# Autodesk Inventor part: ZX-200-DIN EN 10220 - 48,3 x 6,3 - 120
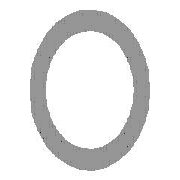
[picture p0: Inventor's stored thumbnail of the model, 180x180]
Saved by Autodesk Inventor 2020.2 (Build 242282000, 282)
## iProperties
Manager: www.cadconsulting.pl
Company: Fabian Stasiak CAD Consulting
IsCustomPart: 1
Created: 2015-02
Part Number: ZX-200-DIN EN 10220 - 48,3 x 6,3 - 120
Material: Stal, miękka
Description: Rury spawane bez szwu - Szereg 1
Document SubType Name: Modeling
Standard: DIN EN 10220
Designer: F.Stasiak
Standard Revision: 2003-03
Standards Organization: DIN
Language: pl-PL
Size Designation: 60,3 x 5,4 - 120
Categories: <MemberInstance><Categories><Category DisplayName="Kształtowniki konstrukcyjne" InternalName="089c4875-fa83-4c05-b084-43b9cc11f5ed" Mnemonic="GRDR"><CategoryPar
Stock Number: 60,3 x 5,4
Density: 7.85 g/cm^3
Appearance: Częściowo polerowany
Catalog Web Link: www.expertbooks.pl
G_L: 120,000 mm
Author: F.Stasiak
Subject: Zbiór ćwiczeń. Autodesk Inventor 2020. Kurs Professional
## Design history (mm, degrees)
node "Płaszczyzna początkowa"
node "Płaszczyzna końcowa"
sketch "Szkic"
  geometry: C1 r 24.75 at (0, 0); C2 r 30.15 at (0, 0); 2 further points
  constraints: 3 coincident, 2 centre point
  dimensions: "d0" = 60.3 diameter of C2 (= G_H); "d1" = 5.4 radial gap between concentric circles of C2 C1 (= G_T)
extrude "Bryła" new body sketch "Szkic" stored distance "d2" = 120 (= G_L); taper "d3" = 0 deg
node "Driven Length"
  sketch "Sketch3"
    geometry: L1 (0, 0)-(10, 0) reference
    constraints: 2 end point, 1 horizontal
  workplane "Work Plane3"
  sketch "Sketch4"
    geometry: L1 (-2, 0)-(12, 0) reference; L2 (-2, 120)-(12, 120) reference
    dimensions: "d7" = 120 distance between parallel lines of L1 L2 (derived)
body "Solid1"
other parameters: "G_H" = 60.3 [user parameter; used in 1 equation term], "G_T" = 5.4 [user parameter; used in 1 equation term], "G_L" = 120 (= d7) [user parameter; used in 1 equation term], "G_OFFSET_START" = 0 [user parameter; used in 1 equation term], "G_OFFSET_END" = 0 [user parameter; used in 1 equation term], "d4" = 0 (computed from G_OFFSET_START), "d6" = 90 deg
